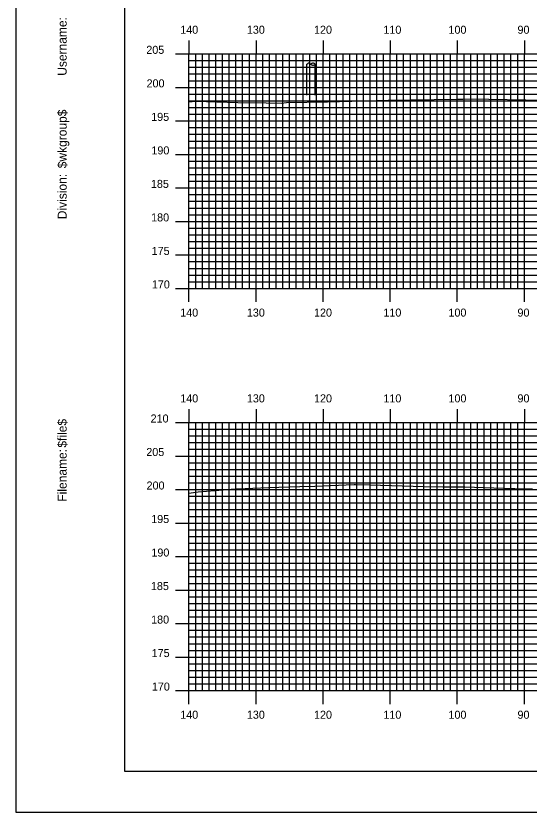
# Model space of a CAD drawing. Extents: x 1796420 to 1796763, y 442591 to 442811.
# Drawn here: x 1796420.1 to 1796496.6, y 442590.5 to 442709.3 of the extents above; entities that cross this region are included whole.
import ezdxf

# ---------------------------------------------------------------- set-up
doc = ezdxf.new("R2010")
doc.units = 0
for name, color, linetype in [('BORDER', 7, 'Continuous'), ('H_V ANNOTATION', 7, 'Continuous'), ('MAJOR', 7, 'Continuous'), ('MINOR', 7, 'Continuous'), ('PLOT BOUNDARY', 7, 'Continuous'), ('S_Roadway_Centerline', 7, 'Continuous'), ('S_Utilities_Pole_Power', 7, 'Continuous')]:
    doc.layers.add(name, color=color, linetype=linetype)

msp = doc.modelspace()

# ---------------------------------------------------------------- linework, layer by layer
at = {"layer": 'BORDER'}
msp.add_lwpolyline([(1796436.31, 442596.67), (1796756.31, 442596.67), (1796756.31, 442806.67), (1796436.31, 442806.67)], close=True, dxfattribs=at)
at = {"layer": 'MAJOR'}
for p, q in [((1796445.91, 442705.67), (1796445.91, 442703.67)), ((1796455.91, 442705.67), (1796455.91, 442703.67)), ((1796465.91, 442705.67), (1796465.91, 442703.67)), ((1796475.91, 442705.67), (1796475.91, 442703.67)), ((1796485.91, 442705.67), (1796485.91, 442703.67)), ((1796495.91, 442705.67), (1796495.91, 442703.67)), ((1796443.9, 442703.67), (1796445.91, 442703.67)), ((1796445.91, 442703.67), (1796725.91, 442703.67)), ((1796445.91, 442668.67), (1796445.91, 442703.67)), ((1796445.91, 442668.67), (1796445.91, 442703.67)), ((1796445.91, 442703.67), (1796725.91, 442703.67)), ((1796455.91, 442668.67), (1796455.91, 442703.67)), ((1796465.91, 442668.67), (1796465.91, 442703.67)), ((1796475.91, 442668.67), (1796475.91, 442703.67)), ((1796485.91, 442668.67), (1796485.91, 442703.67)), ((1796495.91, 442668.67), (1796495.91, 442703.67)), ((1796443.9, 442698.67), (1796445.91, 442698.67)), ((1796445.91, 442698.67), (1796725.91, 442698.67)), ((1796443.9, 442693.67), (1796445.91, 442693.67)), ((1796445.91, 442693.67), (1796725.91, 442693.67)), ((1796443.9, 442688.67), (1796445.91, 442688.67)), ((1796445.91, 442688.67), (1796725.91, 442688.67)), ((1796443.9, 442683.67), (1796445.91, 442683.67)), ((1796445.91, 442683.67), (1796725.91, 442683.67)), ((1796443.9, 442678.67), (1796445.91, 442678.67)), ((1796445.91, 442678.67), (1796725.91, 442678.67)), ((1796443.9, 442673.67), (1796445.91, 442673.67)), ((1796445.91, 442673.67), (1796725.91, 442673.67)), ((1796443.9, 442668.67), (1796445.91, 442668.67)), ((1796445.91, 442668.67), (1796725.91, 442668.67)), ((1796445.91, 442668.67), (1796725.91, 442668.67)), ((1796445.91, 442666.66), (1796445.91, 442668.67)), ((1796455.91, 442666.66), (1796455.91, 442668.67)), ((1796465.91, 442666.66), (1796465.91, 442668.67)), ((1796475.91, 442666.66), (1796475.91, 442668.67)), ((1796485.91, 442666.66), (1796485.91, 442668.67)), ((1796495.91, 442666.66), (1796495.91, 442668.67)), ((1796445.91, 442650.67), (1796445.91, 442648.67)), ((1796455.91, 442650.67), (1796455.91, 442648.67)), ((1796465.91, 442650.67), (1796465.91, 442648.67)), ((1796475.91, 442650.67), (1796475.91, 442648.67)), ((1796485.91, 442650.67), (1796485.91, 442648.67)), ((1796495.91, 442650.67), (1796495.91, 442648.67)), ((1796443.9, 442648.67), (1796445.91, 442648.67)), ((1796445.91, 442648.67), (1796725.91, 442648.67)), ((1796445.91, 442608.67), (1796445.91, 442648.67)), ((1796445.91, 442608.67), (1796445.91, 442648.67)), ((1796445.91, 442648.67), (1796725.91, 442648.67)), ((1796455.91, 442608.67), (1796455.91, 442648.67)), ((1796465.91, 442608.67), (1796465.91, 442648.67)), ((1796475.91, 442608.67), (1796475.91, 442648.67)), ((1796485.91, 442608.67), (1796485.91, 442648.67)), ((1796495.91, 442608.67), (1796495.91, 442648.67)), ((1796443.9, 442643.67), (1796445.91, 442643.67)), ((1796445.91, 442643.67), (1796725.91, 442643.67)), ((1796443.9, 442638.67), (1796445.91, 442638.67)), ((1796445.91, 442638.67), (1796725.91, 442638.67)), ((1796443.9, 442633.67), (1796445.91, 442633.67)), ((1796445.91, 442633.67), (1796725.91, 442633.67)), ((1796443.9, 442628.67), (1796445.91, 442628.67)), ((1796445.91, 442628.67), (1796725.91, 442628.67)), ((1796443.9, 442623.67), (1796445.91, 442623.67)), ((1796445.91, 442623.67), (1796725.91, 442623.67)), ((1796443.9, 442618.67), (1796445.91, 442618.67)), ((1796445.91, 442618.67), (1796725.91, 442618.67)), ((1796443.9, 442613.67), (1796445.91, 442613.67)), ((1796445.91, 442613.67), (1796725.91, 442613.67)), ((1796443.9, 442608.67), (1796445.91, 442608.67)), ((1796445.91, 442608.67), (1796725.91, 442608.67)), ((1796445.91, 442608.67), (1796725.91, 442608.67)), ((1796445.91, 442606.66), (1796445.91, 442608.67)), ((1796455.91, 442606.66), (1796455.91, 442608.67)), ((1796465.91, 442606.66), (1796465.91, 442608.67)), ((1796475.91, 442606.66), (1796475.91, 442608.67)), ((1796485.91, 442606.66), (1796485.91, 442608.67)), ((1796495.91, 442606.66), (1796495.91, 442608.67))]:
    msp.add_line(p, q, dxfattribs=at)
at = {"layer": 'MINOR'}
for p, q in [((1796445.91, 442702.67), (1796725.91, 442702.67)), ((1796445.91, 442702.67), (1796447.91, 442702.67)), ((1796446.91, 442668.67), (1796446.91, 442703.67)), ((1796447.91, 442668.67), (1796447.91, 442703.67)), ((1796448.91, 442668.67), (1796448.91, 442703.67)), ((1796449.91, 442668.67), (1796449.91, 442703.67)), ((1796450.91, 442668.67), (1796450.91, 442703.67)), ((1796451.91, 442668.67), (1796451.91, 442703.67)), ((1796452.91, 442668.67), (1796452.91, 442703.67)), ((1796453.91, 442668.67), (1796453.91, 442703.67)), ((1796454.91, 442668.67), (1796454.91, 442703.67)), ((1796456.91, 442668.67), (1796456.91, 442703.67)), ((1796457.91, 442668.67), (1796457.91, 442703.67)), ((1796458.91, 442668.67), (1796458.91, 442703.67)), ((1796459.91, 442668.67), (1796459.91, 442703.67)), ((1796460.91, 442668.67), (1796460.91, 442703.67)), ((1796461.91, 442668.67), (1796461.91, 442703.67)), ((1796462.91, 442668.67), (1796462.91, 442703.67)), ((1796463.91, 442668.67), (1796463.91, 442703.67)), ((1796464.91, 442668.67), (1796464.91, 442703.67)), ((1796466.91, 442668.67), (1796466.91, 442703.67)), ((1796467.91, 442668.67), (1796467.91, 442703.67)), ((1796468.91, 442668.67), (1796468.91, 442703.67)), ((1796469.91, 442668.67), (1796469.91, 442703.67)), ((1796470.91, 442668.67), (1796470.91, 442703.67)), ((1796471.91, 442668.67), (1796471.91, 442703.67)), ((1796472.91, 442668.67), (1796472.91, 442703.67)), ((1796473.91, 442668.67), (1796473.91, 442703.67)), ((1796474.91, 442668.67), (1796474.91, 442703.67)), ((1796476.91, 442668.67), (1796476.91, 442703.67)), ((1796477.91, 442668.67), (1796477.91, 442703.67)), ((1796478.91, 442668.67), (1796478.91, 442703.67)), ((1796479.91, 442668.67), (1796479.91, 442703.67)), ((1796480.91, 442668.67), (1796480.91, 442703.67)), ((1796481.91, 442668.67), (1796481.91, 442703.67)), ((1796482.91, 442668.67), (1796482.91, 442703.67)), ((1796483.91, 442668.67), (1796483.91, 442703.67)), ((1796484.91, 442668.67), (1796484.91, 442703.67)), ((1796486.91, 442668.67), (1796486.91, 442703.67)), ((1796487.91, 442668.67), (1796487.91, 442703.67)), ((1796488.91, 442668.67), (1796488.91, 442703.67)), ((1796489.91, 442668.67), (1796489.91, 442703.67)), ((1796490.91, 442668.67), (1796490.91, 442703.67)), ((1796491.91, 442668.67), (1796491.91, 442703.67)), ((1796492.91, 442668.67), (1796492.91, 442703.67)), ((1796493.91, 442668.67), (1796493.91, 442703.67)), ((1796494.91, 442668.67), (1796494.91, 442703.67)), ((1796445.91, 442701.67), (1796725.91, 442701.67)), ((1796445.91, 442701.67), (1796447.91, 442701.67)), ((1796445.91, 442700.67), (1796725.91, 442700.67)), ((1796445.91, 442700.67), (1796447.91, 442700.67)), ((1796445.91, 442699.67), (1796725.91, 442699.67)), ((1796445.91, 442699.67), (1796447.91, 442699.67)), ((1796445.91, 442697.67), (1796725.91, 442697.67)), ((1796445.91, 442697.67), (1796447.91, 442697.67)), ((1796445.91, 442696.67), (1796725.91, 442696.67)), ((1796445.91, 442696.67), (1796447.91, 442696.67)), ((1796445.91, 442695.67), (1796725.91, 442695.67)), ((1796445.91, 442695.67), (1796447.91, 442695.67)), ((1796445.91, 442694.67), (1796725.91, 442694.67)), ((1796445.91, 442694.67), (1796447.91, 442694.67)), ((1796445.91, 442692.67), (1796725.91, 442692.67)), ((1796445.91, 442692.67), (1796447.91, 442692.67)), ((1796445.91, 442691.67), (1796725.91, 442691.67)), ((1796445.91, 442691.67), (1796447.91, 442691.67)), ((1796445.91, 442690.67), (1796725.91, 442690.67)), ((1796445.91, 442690.67), (1796447.91, 442690.67)), ((1796445.91, 442689.67), (1796725.91, 442689.67)), ((1796445.91, 442689.67), (1796447.91, 442689.67)), ((1796445.91, 442687.67), (1796725.91, 442687.67)), ((1796445.91, 442687.67), (1796447.91, 442687.67)), ((1796445.91, 442686.67), (1796725.91, 442686.67)), ((1796445.91, 442686.67), (1796447.91, 442686.67)), ((1796445.91, 442685.67), (1796725.91, 442685.67)), ((1796445.91, 442685.67), (1796447.91, 442685.67)), ((1796445.91, 442684.67), (1796725.91, 442684.67)), ((1796445.91, 442684.67), (1796447.91, 442684.67)), ((1796445.91, 442682.67), (1796725.91, 442682.67)), ((1796445.91, 442682.67), (1796447.91, 442682.67)), ((1796445.91, 442681.67), (1796725.91, 442681.67)), ((1796445.91, 442681.67), (1796447.91, 442681.67)), ((1796445.91, 442680.67), (1796725.91, 442680.67)), ((1796445.91, 442680.67), (1796447.91, 442680.67)), ((1796445.91, 442679.67), (1796725.91, 442679.67)), ((1796445.91, 442679.67), (1796447.91, 442679.67)), ((1796445.91, 442677.67), (1796725.91, 442677.67)), ((1796445.91, 442677.67), (1796447.91, 442677.67)), ((1796445.91, 442676.67), (1796725.91, 442676.67)), ((1796445.91, 442676.67), (1796447.91, 442676.67)), ((1796445.91, 442675.67), (1796725.91, 442675.67)), ((1796445.91, 442675.67), (1796447.91, 442675.67)), ((1796445.91, 442674.67), (1796725.91, 442674.67)), ((1796445.91, 442674.67), (1796447.91, 442674.67)), ((1796445.91, 442672.67), (1796725.91, 442672.67)), ((1796445.91, 442672.67), (1796447.91, 442672.67)), ((1796445.91, 442671.67), (1796725.91, 442671.67)), ((1796445.91, 442671.67), (1796447.91, 442671.67)), ((1796445.91, 442670.67), (1796725.91, 442670.67)), ((1796445.91, 442670.67), (1796447.91, 442670.67)), ((1796445.91, 442669.67), (1796725.91, 442669.67)), ((1796445.91, 442669.67), (1796447.91, 442669.67)), ((1796446.91, 442608.67), (1796446.91, 442648.67)), ((1796447.91, 442608.67), (1796447.91, 442648.67)), ((1796448.91, 442608.67), (1796448.91, 442648.67)), ((1796449.91, 442608.67), (1796449.91, 442648.67)), ((1796450.91, 442608.67), (1796450.91, 442648.67)), ((1796451.91, 442608.67), (1796451.91, 442648.67)), ((1796452.91, 442608.67), (1796452.91, 442648.67)), ((1796453.91, 442608.67), (1796453.91, 442648.67)), ((1796454.91, 442608.67), (1796454.91, 442648.67)), ((1796456.91, 442608.67), (1796456.91, 442648.67)), ((1796457.91, 442608.67), (1796457.91, 442648.67)), ((1796458.91, 442608.67), (1796458.91, 442648.67)), ((1796459.91, 442608.67), (1796459.91, 442648.67)), ((1796460.91, 442608.67), (1796460.91, 442648.67)), ((1796461.91, 442608.67), (1796461.91, 442648.67)), ((1796462.91, 442608.67), (1796462.91, 442648.67)), ((1796463.91, 442608.67), (1796463.91, 442648.67)), ((1796464.91, 442608.67), (1796464.91, 442648.67)), ((1796466.91, 442608.67), (1796466.91, 442648.67)), ((1796467.91, 442608.67), (1796467.91, 442648.67)), ((1796468.91, 442608.67), (1796468.91, 442648.67)), ((1796469.91, 442608.67), (1796469.91, 442648.67)), ((1796470.91, 442608.67), (1796470.91, 442648.67)), ((1796471.91, 442608.67), (1796471.91, 442648.67)), ((1796472.91, 442608.67), (1796472.91, 442648.67)), ((1796473.91, 442608.67), (1796473.91, 442648.67)), ((1796474.91, 442608.67), (1796474.91, 442648.67)), ((1796476.91, 442608.67), (1796476.91, 442648.67)), ((1796477.91, 442608.67), (1796477.91, 442648.67)), ((1796478.91, 442608.67), (1796478.91, 442648.67)), ((1796479.91, 442608.67), (1796479.91, 442648.67)), ((1796480.91, 442608.67), (1796480.91, 442648.67)), ((1796481.91, 442608.67), (1796481.91, 442648.67)), ((1796482.91, 442608.67), (1796482.91, 442648.67)), ((1796483.91, 442608.67), (1796483.91, 442648.67)), ((1796484.91, 442608.67), (1796484.91, 442648.67)), ((1796486.91, 442608.67), (1796486.91, 442648.67)), ((1796487.91, 442608.67), (1796487.91, 442648.67)), ((1796488.91, 442608.67), (1796488.91, 442648.67)), ((1796489.91, 442608.67), (1796489.91, 442648.67)), ((1796490.91, 442608.67), (1796490.91, 442648.67)), ((1796491.91, 442608.67), (1796491.91, 442648.67)), ((1796492.91, 442608.67), (1796492.91, 442648.67)), ((1796493.91, 442608.67), (1796493.91, 442648.67)), ((1796494.91, 442608.67), (1796494.91, 442648.67)), ((1796445.91, 442647.67), (1796725.91, 442647.67)), ((1796445.91, 442647.67), (1796447.91, 442647.67)), ((1796445.91, 442646.67), (1796725.91, 442646.67)), ((1796445.91, 442646.67), (1796447.91, 442646.67)), ((1796445.91, 442645.67), (1796725.91, 442645.67)), ((1796445.91, 442645.67), (1796447.91, 442645.67)), ((1796445.91, 442644.67), (1796725.91, 442644.67)), ((1796445.91, 442644.67), (1796447.91, 442644.67)), ((1796445.91, 442642.67), (1796725.91, 442642.67)), ((1796445.91, 442642.67), (1796447.91, 442642.67)), ((1796445.91, 442641.67), (1796725.91, 442641.67)), ((1796445.91, 442641.67), (1796447.91, 442641.67)), ((1796445.91, 442640.67), (1796725.91, 442640.67)), ((1796445.91, 442640.67), (1796447.91, 442640.67)), ((1796445.91, 442639.67), (1796725.91, 442639.67)), ((1796445.91, 442639.67), (1796447.91, 442639.67)), ((1796445.91, 442637.67), (1796447.91, 442637.67)), ((1796445.91, 442637.67), (1796725.91, 442637.67)), ((1796445.91, 442636.67), (1796725.91, 442636.67)), ((1796445.91, 442636.67), (1796447.91, 442636.67)), ((1796445.91, 442635.67), (1796725.91, 442635.67)), ((1796445.91, 442635.67), (1796447.91, 442635.67)), ((1796445.91, 442634.67), (1796725.91, 442634.67)), ((1796445.91, 442634.67), (1796447.91, 442634.67)), ((1796445.91, 442632.67), (1796725.91, 442632.67)), ((1796445.91, 442632.67), (1796447.91, 442632.67)), ((1796445.91, 442631.67), (1796725.91, 442631.67)), ((1796445.91, 442631.67), (1796447.91, 442631.67)), ((1796445.91, 442630.67), (1796725.91, 442630.67)), ((1796445.91, 442630.67), (1796447.91, 442630.67)), ((1796445.91, 442629.67), (1796725.91, 442629.67)), ((1796445.91, 442629.67), (1796447.91, 442629.67)), ((1796445.91, 442627.67), (1796725.91, 442627.67)), ((1796445.91, 442627.67), (1796447.91, 442627.67)), ((1796445.91, 442626.67), (1796725.91, 442626.67)), ((1796445.91, 442626.67), (1796447.91, 442626.67)), ((1796445.91, 442625.67), (1796725.91, 442625.67)), ((1796445.91, 442625.67), (1796447.91, 442625.67)), ((1796445.91, 442624.67), (1796725.91, 442624.67)), ((1796445.91, 442624.67), (1796447.91, 442624.67)), ((1796445.91, 442622.67), (1796725.91, 442622.67)), ((1796445.91, 442622.67), (1796447.91, 442622.67)), ((1796445.91, 442621.67), (1796725.91, 442621.67)), ((1796445.91, 442621.67), (1796447.91, 442621.67)), ((1796445.91, 442620.67), (1796725.91, 442620.67)), ((1796445.91, 442620.67), (1796447.91, 442620.67)), ((1796445.91, 442619.67), (1796725.91, 442619.67)), ((1796445.91, 442619.67), (1796447.91, 442619.67)), ((1796445.91, 442617.67), (1796725.91, 442617.67)), ((1796445.91, 442617.67), (1796447.91, 442617.67)), ((1796445.91, 442616.67), (1796725.91, 442616.67)), ((1796445.91, 442616.67), (1796447.91, 442616.67)), ((1796445.91, 442615.67), (1796725.91, 442615.67)), ((1796445.91, 442615.67), (1796447.91, 442615.67)), ((1796445.91, 442614.67), (1796725.91, 442614.67)), ((1796445.91, 442614.67), (1796447.91, 442614.67)), ((1796445.91, 442612.67), (1796725.91, 442612.67)), ((1796445.91, 442612.67), (1796447.91, 442612.67)), ((1796445.91, 442611.67), (1796725.91, 442611.67)), ((1796445.91, 442611.67), (1796447.91, 442611.67)), ((1796445.91, 442610.67), (1796725.91, 442610.67)), ((1796445.91, 442610.67), (1796447.91, 442610.67)), ((1796445.91, 442609.67), (1796725.91, 442609.67)), ((1796445.91, 442609.67), (1796447.91, 442609.67))]:
    msp.add_line(p, q, dxfattribs=at)
at = {"layer": 'PLOT BOUNDARY'}
msp.add_lwpolyline([(1796420.12, 442590.55), (1796760.12, 442590.55), (1796760.12, 442810.55), (1796420.12, 442810.55)], close=True, dxfattribs=at)
at = {"layer": 'S_Roadway_Centerline'}
for points in [[(1796445.91, 442696.52), (1796446.94, 442696.61), (1796453.17, 442696.42), (1796457.4, 442696.36), (1796459.72, 442696.31), (1796459.72, 442696.31), (1796460.47, 442696.41), (1796466.57, 442696.5), (1796475.61, 442696.74), (1796485.91, 442696.93), (1796486.71, 442696.93), (1796487.88, 442696.94), (1796498.86, 442696.78)], [(1796445.91, 442638.12), (1796447.29, 442638.33), (1796450.99, 442638.62), (1796452.8, 442638.78), (1796453.08, 442638.78), (1796457.79, 442638.96), (1796462.44, 442639.12), (1796464.68, 442639.18), (1796470.54, 442639.4), (1796470.71, 442639.42), (1796472.82, 442639.36), (1796480.98, 442639.14), (1796483.76, 442639.08), (1796487.01, 442639.06), (1796494.22, 442638.84), (1796494.48, 442638.83), (1796494.5, 442638.83), (1796497.11, 442638.76)]]:
    msp.add_lwpolyline(points, dxfattribs=at)
at = {"layer": 'S_Utilities_Pole_Power'}
for p, q in [((1796463.46, 442702.14), (1796463.62, 442702.25)), ((1796463.46, 442697.52), (1796463.46, 442702.14)), ((1796463.93, 442702.25), (1796464.09, 442702.14)), ((1796464.24, 442702.25), (1796464.09, 442702.14)), ((1796464.09, 442702.14), (1796464.24, 442702.03)), ((1796464.71, 442702.14), (1796464.56, 442702.25)), ((1796464.56, 442702.03), (1796464.71, 442702.14)), ((1796464.71, 442697.52), (1796464.71, 442702.14))]:
    msp.add_line(p, q, dxfattribs=at)
for centre, start, end in [((1796463.77, 442702.03), 90, 125.2644), ((1796463.77, 442702.03), 54.7356, 90), ((1796464.4, 442702.03), 90, 125.2644), ((1796464.4, 442702.25), 234.7356, 270), ((1796464.4, 442702.03), 54.7356, 90), ((1796464.4, 442702.25), 270, 305.2644)]:
    msp.add_arc(centre, 0.271, start, end, dxfattribs=at)

# ---------------------------------------------------------------- texts
at = {"layer": 'BORDER'}
for s, p in [('Username:', (1796427.68, 442700.4)), ('$wkgroup$', (1796427.68, 442686.6)), ('Division:', (1796427.68, 442679)), ('$file$', (1796427.68, 442644.92)), ('Filename:', (1796427.68, 442636.86))]:
    msp.add_text(s, height=1.339, rotation=90, dxfattribs=at).set_placement(p)
at = {"layer": 'H_V ANNOTATION'}
for s, p in [('140', (1796444.61, 442706.67)), ('130', (1796454.54, 442706.67)), ('120', (1796464.55, 442706.67)), ('110', (1796474.89, 442706.67)), ('100', (1796484.59, 442706.67)), ('90', (1796494.88, 442706.67)), ('205', (1796439.55, 442703.67)), ('200', (1796439.59, 442698.67)), ('195', (1796440.28, 442693.67)), ('190', (1796440.31, 442688.67)), ('185', (1796440.24, 442683.67)), ('180', (1796440.27, 442678.67)), ('175', (1796440.35, 442673.67)), ('170', (1796440.38, 442668.67)), ('140', (1796444.61, 442664.47)), ('130', (1796454.54, 442664.47)), ('120', (1796464.55, 442664.47)), ('110', (1796474.89, 442664.47)), ('100', (1796484.59, 442664.47)), ('90', (1796494.88, 442664.47)), ('140', (1796444.61, 442651.67)), ('130', (1796454.54, 442651.67)), ('120', (1796464.55, 442651.67)), ('110', (1796474.89, 442651.67)), ('100', (1796484.59, 442651.67)), ('90', (1796494.88, 442651.67)), ('210', (1796440.19, 442648.67)), ('205', (1796439.55, 442643.67)), ('200', (1796439.59, 442638.67)), ('195', (1796440.28, 442633.67)), ('190', (1796440.31, 442628.67)), ('185', (1796440.24, 442623.67)), ('180', (1796440.27, 442618.67)), ('175', (1796440.35, 442613.67)), ('170', (1796440.38, 442608.67)), ('140', (1796444.61, 442604.47)), ('130', (1796454.54, 442604.47)), ('120', (1796464.55, 442604.47)), ('110', (1796474.89, 442604.47)), ('100', (1796484.59, 442604.47)), ('90', (1796494.88, 442604.47))]:
    msp.add_text(s, height=1.2, dxfattribs=at).set_placement(p)
at = {"layer": 'MAJOR'}
for p in [(1796445.9, 442668.67), (1796445.9, 442608.67)]:
    msp.add_text('-', height=0.012, dxfattribs=at).set_placement(p)
at = {"layer": 'S_Roadway_Centerline'}
for s, p in [('C', (1796470.7, 442639.42)), ('C', (1796470.7, 442639.42)), ('L', (1796470.71, 442639.41)), ('L', (1796470.71, 442639.41))]:
    msp.add_text(s, height=0.0146, dxfattribs=at).set_placement(p)

doc.saveas('drawing.dxf')
